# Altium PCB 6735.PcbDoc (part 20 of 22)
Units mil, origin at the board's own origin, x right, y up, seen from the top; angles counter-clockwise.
Board outline 2641.73 x 5165.35 mil, 6 copper layers (Top, Inner Layer 2, Inner Layer 3, Inner Layer 4, Inner Layer 5, Bottom), stack 35.7 mil thick; 1011 components, 790 nets, 4118 pads, 9325 vias.
Unrouted connection lines stored in the file: 4610.
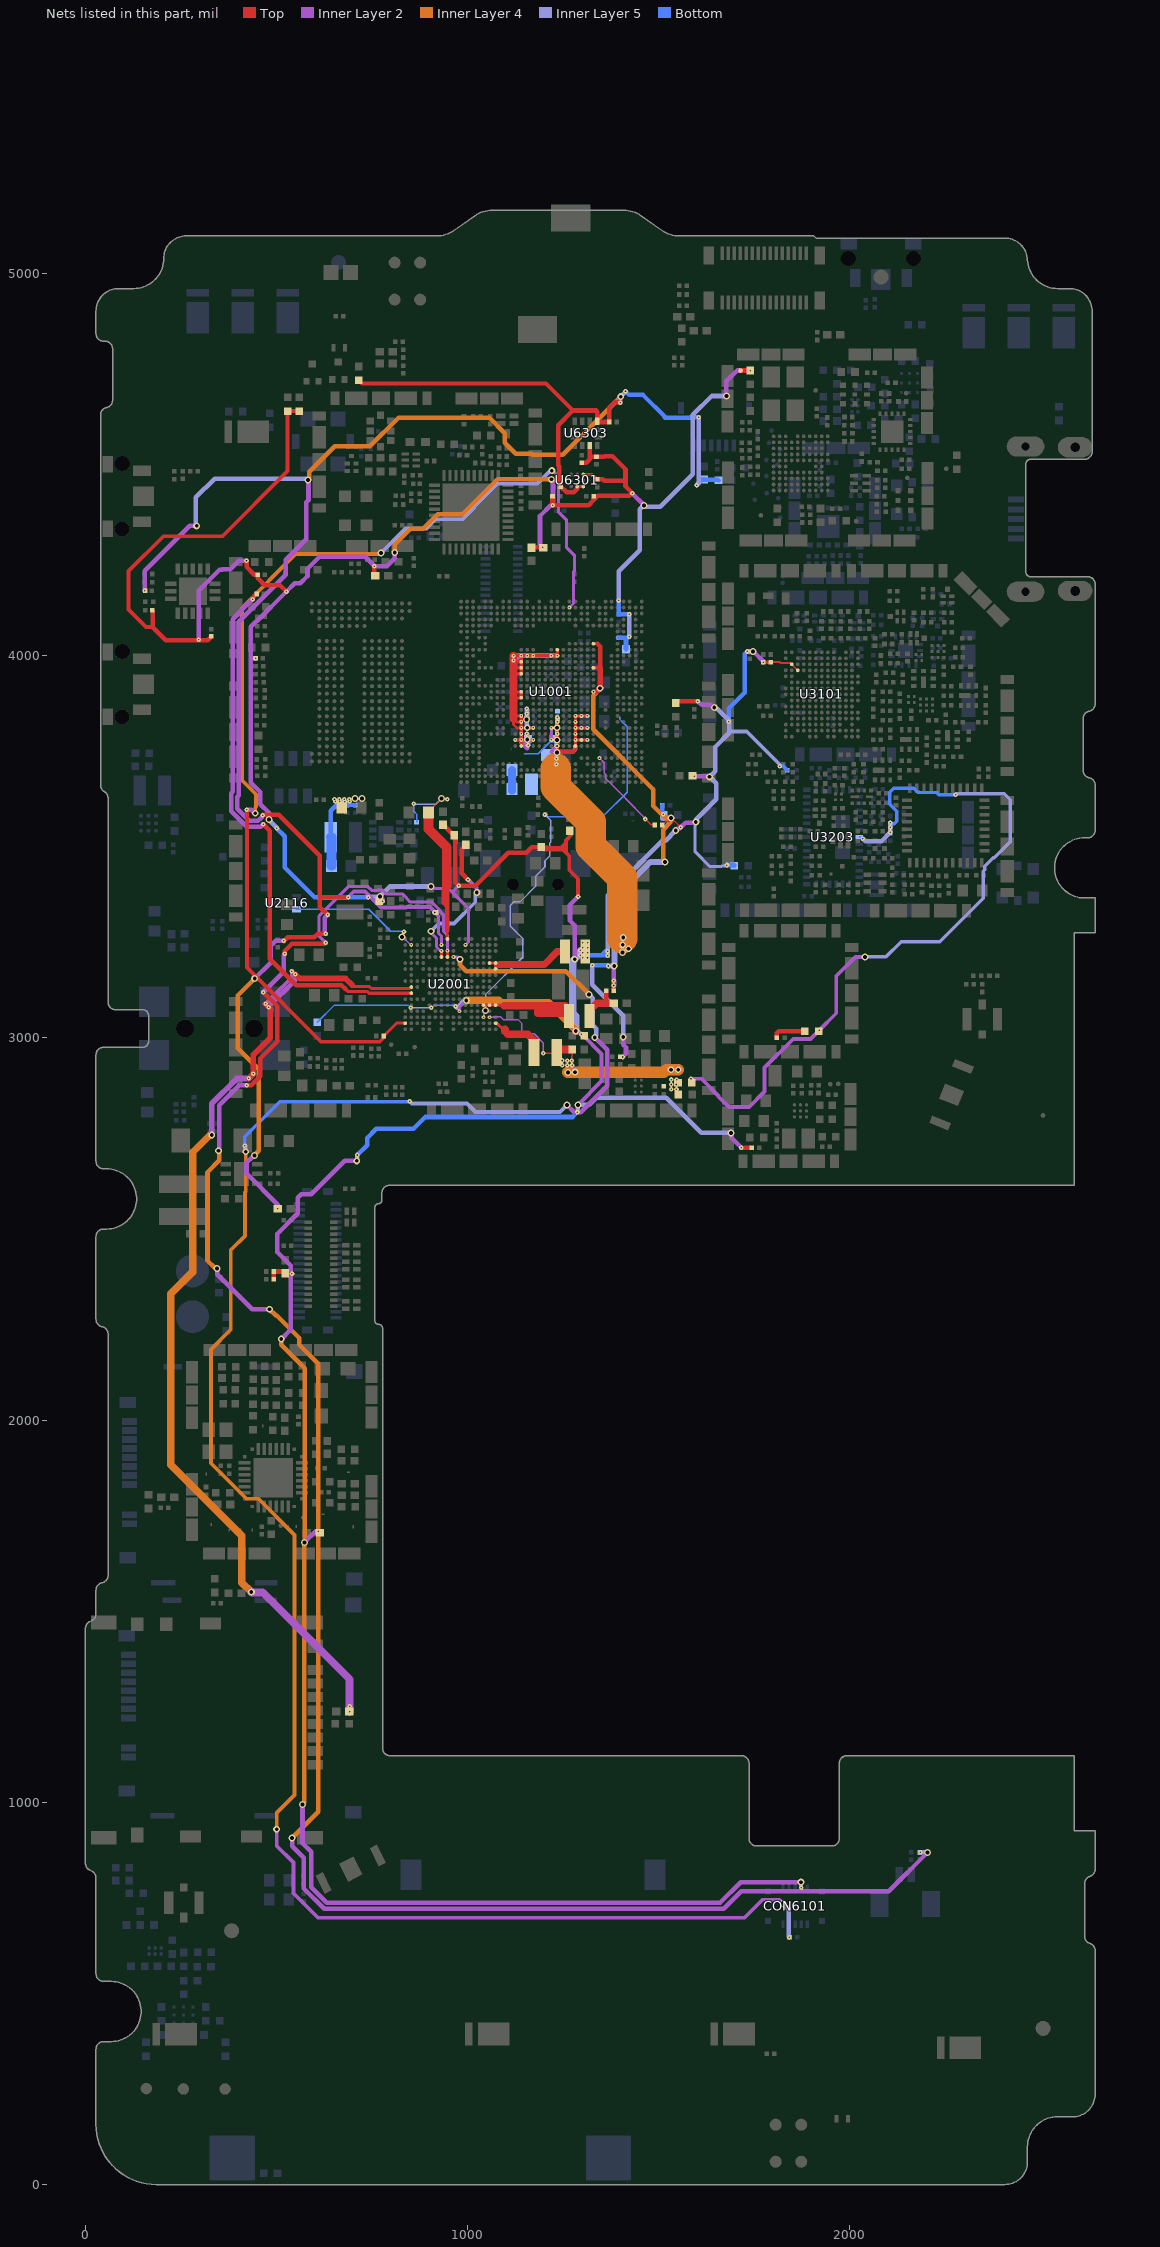
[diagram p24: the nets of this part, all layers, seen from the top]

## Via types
v1: diameter 12, hole 4, Top to Inner Layer 2, 3329 vias
v2: diameter 12, hole 4, Inner Layer 5 to Bottom, 3071 vias
v3: diameter 18, hole 10, Inner Layer 2 to Inner Layer 5, 1928 vias
v4: diameter 10, hole 4, Top to Inner Layer 2, 525 vias
v5: diameter 20, hole 12, Top to Bottom, 472 vias

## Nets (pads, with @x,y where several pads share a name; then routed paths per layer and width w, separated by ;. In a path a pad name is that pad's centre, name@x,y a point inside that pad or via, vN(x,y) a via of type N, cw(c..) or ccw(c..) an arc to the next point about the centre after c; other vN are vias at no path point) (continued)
VCORE_PMU: C10006.1 C10008.1 C10009.1 C10012.1 C10016.1 C10017.1 C10018.1 C10025.1 C10027.1 C10035.1 C10037.1 C10039.1 L2006.2 SH1006.2 U1001.AA8 U1001.AA10 U1001.AA12 U1001.AB8 U1001.AB10 U1001.AB12 U1001.K8 U1001.L7 U1001.L8 U1001.L9 U1001.L10 U1001.L11 U1001.L12 U1001.L15 U1001.L16 U1001.L19 U1001.L20 U1001.L21 U1001.L22 U1001.M8 U1001.M10 U1001.M22 U1001.N8 U1001.N10 U1001.N22 U1001.T8 U1001.T10 U1001.T22 U1001.U7 U1001.U8 U1001.U9 U1001.U10 U1001.U11 U1001.U22 U1001.U23 U1001.Y7 U1001.Y8 U1001.Y9 U1001.Y10 U1001.Y11 U1001.Y12 | length 3265.3
  Top w4: v4(1119.95,3999.49) v4(1119.95,3987.49) 1120.08,3987.36 v4@1120.08,3984.23 ; v4(1140.21,3999.98) v4(1155.96,3999.98) ; U1001.M8@1155.96,3779.51 1165.65,3779.51 ; U1001.M10@1155.96,3811 1163.15,3811 ; U1001.AA8@1297.69,3779.51 1303.15,3779.51 ; v1(1300.76,3209.4) 1302.95,3210.49 L2006.2@1302.95,3220.4 ; v1(1300.85,3235.36) 1301.15,3235.36 1301.15,3248.39 v1(1301.45,3248.39) ; L2006.2@1302.39,3221.26 L2006.2@1301.23,3222.13 ; v1(1313.52,3209.2) 1314.95,3211.49 1314.95,3218.4 L2006.2@1312.07,3221.28 ; v1(1313.98,3248.59) L2006.2@1313.98,3236.06 ; v1(1314.28,3222.22) 1312.97,3222.18 L2006.2@1312.07,3221.28 ; v1(1314.28,3235.96) L2006.2@1313.98,3236.06 ; v1(1300.75,3222.49) L2006.2@1301.02,3222.34 ; v1(1300.75,3222.49) L2006.2@1302.52,3220.83 ; v1(1300.75,3222.49) L2006.2@1301.23,3222.13 ; v1(1300.75,3222.49) L2006.2@1301.24,3222.12 ; v1(1300.75,3222.49) L2006.2@1301.25,3222.12 ; v1(1300.75,3222.49) L2006.2@1300.87,3222.49 ; v1(1300.75,3222.49) L2006.2@1301.03,3222.34 ; v1(1300.75,3222.49) L2006.2@1301.24,3222.12 ; v1(1300.75,3222.49) 1302.65,3220.69 L2006.2@1302.95,3220.4 ; v1(1300.75,3222.49) L2006.2@1301.02,3222.34 ; v1(1300.75,3222.49) L2006.2@1301.09,3222.27 ; v1(1300.75,3222.49) 1302.5,3223.31 1302.18,3223.15 L2006.2@1302.52,3223.32 ; v1(1300.75,3222.49) L2006.2@1301.22,3222.66 ; L2006.2@1300.87,3222.49 L2006.2@1301.02,3222.34 ; L2006.2@1300.87,3222.49 L2006.2@1301.3,3222.49 ; L2006.2@1300.87,3222.49 L2006.2@1301.22,3222.66 ; L2006.2@1300.87,3222.49 L2006.2@1301.22,3222.66 ; L2006.2@1301.02,3222.34 L2006.2@1301.3,3222.49 ; L2006.2@1301.03,3222.34 L2006.2@1301.09,3222.27 ; L2006.2@1301.02,3222.34 L2006.2@1301.15,3222.27 ; L2006.2@1301.03,3222.34 L2006.2@1301.31,3222.18 ; L2006.2@1301.02,3222.34 L2006.2@1301.15,3222.27 ; L2006.2@1301.02,3222.34 L2006.2@1301.3,3222.49 ; L2006.2@1301.09,3222.27 L2006.2@1301.23,3222.13 ; L2006.2@1301.09,3222.27 L2006.2@1301.27,3222.15 ; L2006.2@1301.15,3222.27 L2006.2@1301.31,3222.18 ; L2006.2@1301.15,3222.27 L2006.2@1301.31,3222.18 ; L2006.2@1301.22,3222.66 L2006.2@1302.52,3223.15 ; L2006.2@1301.22,3222.66 L2006.2@1302.52,3223.32 ; L2006.2@1301.22,3222.66 L2006.2@1302.52,3223.32 ; L2006.2@1301.25,3222.12 L2006.2@1302.51,3220.85 ; L2006.2@1301.24,3222.12 L2006.2@1302.52,3221.15 ; L2006.2@1301.25,3222.12 L2006.2@1302.52,3221.15 ; L2006.2@1301.24,3222.12 L2006.2@1302.52,3221.15 ; L2006.2@1301.27,3222.15 L2006.2@1302.52,3221.34 ; L2006.2@1301.31,3222.18 L2006.2@1301.53,3222.05 ; L2006.2@1301.31,3222.18 L2006.2@1301.53,3222.05 ; L2006.2@1301.31,3222.18 L2006.2@1302.52,3221.5 ; L2006.2@1301.31,3222.18 L2006.2@1301.84,3222.49 ; L2006.2@1301.31,3222.18 L2006.2@1301.85,3222.49 ; L2006.2@1301.3,3222.49 L2006.2@1301.84,3222.49 ; L2006.2@1301.3,3222.49 L2006.2@1301.35,3222.52 ; L2006.2@1301.3,3222.49 L2006.2@1302.52,3223.14 ; L2006.2@1301.3,3222.49 L2006.2@1301.35,3222.52 ; L2006.2@1301.35,3222.52 L2006.2@1302.52,3223.15 ; L2006.2@1301.35,3222.52 L2006.2@1302.52,3223.14 ; L2006.2@1301.53,3222.05 L2006.2@1302.52,3221.49 ; L2006.2@1301.53,3222.05 L2006.2@1302.52,3221.49 ; L2006.2@1301.85,3222.49 L2006.2@1302.52,3222.49 ; L2006.2@1301.84,3222.49 L2006.2@1302.52,3222.89 ; L2006.2@1301.85,3222.49 L2006.2@1302.52,3222.89 ; L2006.2@1302.52,3220.83 L2006.2@1302.95,3220.83 ; L2006.2@1302.52,3220.83 L2006.2@1302.52,3221.15 ; L2006.2@1302.52,3220.83 L2006.2@1302.95,3220.4 ; L2006.2@1302.52,3220.83 L2006.2@1302.71,3221.01 ; L2006.2@1302.52,3220.83 L2006.2@1302.71,3221.01 ; L2006.2@1302.52,3221.15 L2006.2@1302.71,3221.01 ; L2006.2@1302.52,3221.15 L2006.2@1302.52,3221.34 ; L2006.2@1302.53,3221.15 L2006.2@1302.71,3221.01 ; L2006.2@1302.53,3221.15 L2006.2@1302.64,3221.26 ; L2006.2@1302.52,3221.34 L2006.2@1302.52,3221.49 ; L2006.2@1302.52,3221.34 L2006.2@1302.64,3221.26 ; L2006.2@1302.53,3221.49 L2006.2@1302.75,3221.36 ; L2006.2@1302.52,3221.49 L2006.2@1302.75,3221.36 ; L2006.2@1302.52,3221.5 L2006.2@1302.52,3222.49 ; L2006.2@1302.52,3222.49 L2006.2@1303.67,3222.49 ; L2006.2@1302.52,3222.49 L2006.2@1302.52,3222.89 ; L2006.2@1302.52,3222.49 L2006.2@1307.53,3225.83 ; L2006.2@1302.52,3222.49 L2006.2@1307.53,3225.83 ; L2006.2@1302.52,3222.89 L2006.2@1302.52,3223.14 ; L2006.2@1302.52,3222.89 L2006.2@1307.53,3225.83 ; L2006.2@1302.52,3222.89 L2006.2@1307.53,3225.83 ; L2006.2@1302.52,3223.15 L2006.2@1302.52,3223.32 ; L2006.2@1302.52,3223.14 L2006.2@1307.53,3225.83 ; L2006.2@1302.52,3223.15 L2006.2@1307.53,3225.83 ; L2006.2@1302.52,3223.15 L2006.2@1307.45,3225.79 ; L2006.2@1302.52,3223.14 L2006.2@1307.53,3225.83 ; L2006.2@1302.52,3223.32 L2006.2@1307.53,3225.83 ; L2006.2@1302.52,3223.32 1302.52,3225.91 1304.99,3228.37 1306.41,3229.8 1312.98,3236.36 L2006.2@1313.98,3236.06 ; L2006.2@1302.52,3223.32 L2006.2@1307.53,3225.83 ; L2006.2@1302.52,3223.32 L2006.2@1304.26,3224.19 ; L2006.2@1302.52,3223.32 L2006.2@1304.26,3224.19 ; L2006.2@1302.52,3223.32 L2006.2@1307.45,3225.79 ; L2006.2@1302.53,3221.5 L2006.2@1302.76,3221.37 ; L2006.2@1302.53,3221.5 L2006.2@1303.67,3222.49 ; L2006.2@1302.53,3221.5 L2006.2@1303.68,3222.49 ; L2006.2@1302.64,3221.26 L2006.2@1302.83,3221.14 ; L2006.2@1302.64,3221.26 L2006.2@1302.75,3221.36 ; L2006.2@1302.71,3221.01 L2006.2@1302.95,3220.83 ; L2006.2@1302.71,3221.01 L2006.2@1302.95,3220.83 ; L2006.2@1302.71,3221.01 L2006.2@1302.83,3221.14 ; L2006.2@1302.71,3221.01 L2006.2@1302.83,3221.14 ; L2006.2@1302.71,3221.01 L2006.2@1302.84,3221.14 ; L2006.2@1302.75,3221.36 1302.9,3221.28 L2006.2@1302.75,3221.36 ; L2006.2@1302.76,3221.37 L2006.2@1302.95,3221.26 ; L2006.2@1302.76,3221.37 L2006.2@1303.96,3222.49 ; L2006.2@1302.84,3221.14 L2006.2@1302.95,3221.06 ; L2006.2@1302.84,3221.14 L2006.2@1302.95,3221.25 ; L2006.2@1302.83,3221.14 L2006.2@1302.95,3221.26 ; L2006.2@1302.84,3221.15 L2006.2@1302.95,3221.26 ; L2006.2@1302.84,3221.15 L2006.2@1302.95,3221.26 ; L2006.2@1302.84,3221.14 L2006.2@1302.95,3221.25 ; L2006.2@1302.95,3220.4 L2006.2@1302.95,3220.83 ; L2006.2@1302.95,3220.4 1304.87,3218.49 1309.27,3218.49 L2006.2@1312.07,3221.27 ; L2006.2@1302.95,3220.4 L2006.2@1303.07,3220.54 ; L2006.2@1302.95,3220.4 L2006.2@1303.07,3220.54 ; L2006.2@1302.95,3220.83 L2006.2@1303.31,3220.83 ; L2006.2@1302.95,3220.83 L2006.2@1302.95,3221.06 ; L2006.2@1302.95,3220.83 L2006.2@1303.09,3220.98 ; L2006.2@1302.95,3221.06 L2006.2@1302.95,3221.25 ; L2006.2@1302.95,3221.06 L2006.2@1303.09,3220.98 ; L2006.2@1302.95,3221.25 L2006.2@1303.32,3221.62 ; L2006.2@1302.95,3221.26 L2006.2@1304.04,3222.34 ; L2006.2@1302.95,3221.26 L2006.2@1304.18,3222.49 ; L2006.2@1302.95,3221.26 L2006.2@1304.06,3222.37 ; L2006.2@1302.95,3221.25 L2006.2@1303.25,3221.55 ; L2006.2@1302.95,3221.26 L2006.2@1304.07,3222.37 ; L2006.2@1303.07,3220.54 L2006.2@1303.31,3220.83 ; L2006.2@1303.07,3220.54 L2006.2@1303.32,3220.83 ; L2006.2@1303.09,3220.98 L2006.2@1303.31,3220.83 ; L2006.2@1303.09,3220.98 L2006.2@1304.47,3222.49 ; L2006.2@1303.09,3220.98 L2006.2@1304.47,3222.49 ; L2006.2@1303.25,3221.55 1303.19,3221.49 L2006.2@1303.61,3221.91 ; L2006.2@1303.25,3221.55 L2006.2@1303.32,3221.62 ; L2006.2@1303.25,3221.55 L2006.2@1303.61,3221.91 ; L2006.2@1303.32,3220.83 1304.18,3220.83 L2006.2@1305.84,3222.49 ; L2006.2@1303.31,3220.83 L2006.2@1304.23,3221.91 ; L2006.2@1303.31,3220.83 L2006.2@1304.23,3221.91 ; L2006.2@1303.32,3220.83 L2006.2@1304.71,3222.49 ; L2006.2@1303.31,3220.83 L2006.2@1304.51,3222.25 ; L2006.2@1303.31,3220.83 L2006.2@1304.71,3222.49 ; L2006.2@1303.32,3221.62 L2006.2@1304.04,3222.34 ; L2006.2@1303.32,3221.62 L2006.2@1304.19,3222.49 ; L2006.2@1303.61,3221.91 L2006.2@1304.19,3222.49 ; L2006.2@1303.61,3221.91 L2006.2@1304.19,3222.49 ; L2006.2@1303.68,3222.49 L2006.2@1303.96,3222.49 ; L2006.2@1303.67,3222.49 L2006.2@1307.53,3225.83 ; L2006.2@1303.68,3222.49 L2006.2@1307.53,3225.83 ; L2006.2@1303.96,3222.49 L2006.2@1304.18,3222.49 ; L2006.2@1303.96,3222.49 L2006.2@1307.53,3225.83 ; L2006.2@1304.04,3222.34 L2006.2@1304.18,3222.49 ; L2006.2@1304.07,3222.37 L2006.2@1304.18,3222.49 ; L2006.2@1304.06,3222.37 L2006.2@1304.18,3222.49 ; L2006.2@1304.07,3222.37 L2006.2@1304.18,3222.49 ; L2006.2@1304.23,3221.91 L2006.2@1304.71,3222.49 ; L2006.2@1304.23,3221.91 L2006.2@1304.51,3222.25 ; L2006.2@1304.19,3222.49 L2006.2@1304.47,3222.49 ; L2006.2@1304.18,3222.49 L2006.2@1307.53,3225.83 ; L2006.2@1304.19,3222.49 L2006.2@1305.94,3224.25 ; L2006.2@1304.18,3222.49 L2006.2@1305.94,3224.25 ; L2006.2@1304.19,3222.49 L2006.2@1306.06,3224.36 ; L2006.2@1304.18,3222.49 L2006.2@1305.98,3224.28 ; L2006.2@1304.19,3222.49 L2006.2@1307.53,3225.83 ; L2006.2@1304.18,3222.49 L2006.2@1305.99,3224.29 ; L2006.2@1304.18,3222.49 L2006.2@1306.16,3224.46 ; L2006.2@1304.26,3224.19 L2006.2@1307.53,3225.83 ; L2006.2@1304.26,3224.19 L2006.2@1307.53,3225.83 ; L2006.2@1304.47,3222.49 L2006.2@1304.71,3222.49 ; L2006.2@1304.47,3222.49 L2006.2@1305.07,3223.14 ; L2006.2@1304.47,3222.49 L2006.2@1305.07,3223.14 ; L2006.2@1304.47,3222.49 L2006.2@1307.53,3225.83 ; L2006.2@1304.51,3222.25 L2006.2@1304.71,3222.49 ; L2006.2@1304.51,3222.25 L2006.2@1304.71,3222.49 ; L2006.2@1304.71,3222.49 L2006.2@1305.84,3222.49 ; L2006.2@1304.71,3222.49 L2006.2@1305.06,3222.91 ; L2006.2@1304.71,3222.49 L2006.2@1307.53,3225.83 ; L2006.2@1304.71,3222.49 L2006.2@1307.53,3225.83 ; L2006.2@1304.71,3222.49 L2006.2@1305.06,3222.91 ; L2006.2@1304.71,3222.49 L2006.2@1307.53,3225.83 ; L2006.2@1304.71,3222.49 L2006.2@1307.53,3225.83 ; L2006.2@1305.06,3222.91 L2006.2@1307.53,3225.83 ; L2006.2@1305.06,3222.91 L2006.2@1307.53,3225.83 ; L2006.2@1305.07,3223.14 L2006.2@1307.53,3225.83 ; L2006.2@1305.07,3223.14 L2006.2@1307.53,3225.83 ; L2006.2@1305.84,3222.49 1307.52,3222.49 L2006.2@1307.52,3224.17 ; L2006.2@1305.84,3222.49 L2006.2@1307.52,3224.17 ; L2006.2@1305.84,3222.49 1307.44,3225.66 L2006.2@1307.53,3225.83 ; L2006.2@1305.84,3222.49 1307.45,3225.67 L2006.2@1307.53,3225.83 ; L2006.2@1305.94,3224.25 L2006.2@1306.06,3224.36 ; L2006.2@1305.99,3224.29 L2006.2@1306.16,3224.46 ; L2006.2@1305.98,3224.28 L2006.2@1306.08,3224.39 ; L2006.2@1305.99,3224.29 L2006.2@1306.1,3224.4 ; L2006.2@1306.06,3224.36 L2006.2@1307.53,3225.83 ; L2006.2@1306.1,3224.4 L2006.2@1306.24,3224.55 ; L2006.2@1306.08,3224.39 L2006.2@1307.53,3225.83 ; L2006.2@1306.1,3224.4 L2006.2@1307.53,3225.83 ; L2006.2@1306.16,3224.46 L2006.2@1307.53,3225.83 ; L2006.2@1306.16,3224.46 L2006.2@1306.24,3224.55 ; L2006.2@1306.24,3224.55 L2006.2@1307.53,3225.83 ; L2006.2@1306.24,3224.55 L2006.2@1307.53,3225.83 ; L2006.2@1307.53,3225.83 L2006.2@1307.53,3225.83 ; L2006.2@1307.53,3225.83 L2006.2@1307.53,3225.83 ; L2006.2@1307.53,3225.83 L2006.2@1307.53,3225.83 ; L2006.2@1307.53,3225.83 L2006.2@1307.53,3225.83 ; L2006.2@1307.53,3225.83 L2006.2@1307.53,3225.83 ; L2006.2@1307.53,3225.83 L2006.2@1307.53,3225.83 ; L2006.2@1307.53,3225.83 L2006.2@1307.53,3225.83 ; L2006.2@1307.52,3224.17 L2006.2@1308.35,3225 ; L2006.2@1307.52,3224.17 L2006.2@1307.53,3225.83 ; L2006.2@1307.52,3224.17 L2006.2@1307.53,3225.83 ; L2006.2@1307.53,3225.83 L2006.2@1308.35,3225 ; L2006.2@1307.53,3225.83 L2006.2@1308.35,3225 ; L2006.2@1307.53,3225.83 L2006.2@1308.07,3225.28 ; L2006.2@1307.53,3225.83 L2006.2@1308.07,3225.28 ; L2006.2@1307.53,3225.83 L2006.2@1307.82,3226.3 ; L2006.2@1307.53,3225.83 L2006.2@1307.82,3226.3 ; L2006.2@1307.82,3226.3 L2006.2@1313.98,3236.06 ; L2006.2@1307.82,3226.3 L2006.2@1313.98,3236.06 ; L2006.2@1308.07,3225.28 L2006.2@1308.35,3225 ; L2006.2@1308.07,3225.28 L2006.2@1308.35,3225 ; L2006.2@1308.35,3225 L2006.2@1309.13,3224.22 ; L2006.2@1308.35,3225 L2006.2@1308.71,3224.64 ; L2006.2@1308.35,3225 L2006.2@1312.07,3221.28 ; L2006.2@1308.35,3225 L2006.2@1308.71,3224.64 ; L2006.2@1308.35,3225 1313.98,3230.63 L2006.2@1313.98,3236.06 ; L2006.2@1308.71,3224.64 L2006.2@1309.13,3224.22 ; L2006.2@1308.71,3224.64 1310.87,3222.49 L2006.2@1309.13,3224.22 ; L2006.2@1309.13,3224.22 L2006.2@1312.07,3221.28
  Top w8: v4(1119.95,3999.49) 1120.08,3999.97 v4(1140.21,3999.98) ; 1120.08,3842.49 v4(1140.21,3842.5) v4(1140.21,3826.75) ; 1120.08,3889.74 U1001.L15@1140.21,3889.74 U1001.L16@1140.21,3905.49 1124.95,3905.49 ; 1120.08,3952.73 U1001.L19@1140.21,3952.73 U1001.L20@1140.21,3968.48 ; 1120.08,3968.48 U1001.L20@1140.21,3968.48 ; v4@1120.08,3984.23 U1001.L21@1140.21,3984.23 ; v4(1124.46,3779.51) v4(1140.21,3779.51) ; U1001.M8@1155.96,3779.51 v4(1140.21,3779.51) ; 1165.65,3779.51 v4(1171.71,3779.51) ; v4(1171.71,3811) 1163.15,3811 U1001.M10@1155.96,3811 v4(1140.21,3811) ; v4(1218.95,3811) U1001.U10@1234.7,3811 ; 1234.7,3748.23 v4(1234.7,3763.76) U1001.U8@1234.7,3779.51 ; v4(1234.7,3826.75) U1001.U10@1234.7,3811 ; U1001.U23@1234.7,4015.73 v4(1234.7,3999.98) v4(1218.95,3999.98) v4(1171.71,3999.98) v4(1155.96,3999.98) v4(1140.21,3999.98) ; 1275.08,3748.23 1281.94,3755.1 ; U1001.Y7@1281.94,3763.76 1281.94,3755.1 ; v4(1313.44,3779.51) 1303.15,3779.5 U1001.AA8@1297.69,3779.51 v4(1281.94,3779.51) ; v4(1313.44,3811) v4(1297.69,3811) v4(1281.94,3811) ; v4(1313.44,3842.5) v4(1297.69,3842.5) v4(1281.94,3842.5) v4(1281.94,3811) ; 1128.44,3826.75 v4(1140.21,3826.75) ; 1128.44,3826.75 1120.08,3835.1 1120.08,3820.1 1129.19,3811 v4(1140.21,3811) ; 1128.44,3826.75 v4(1140.21,3826.75) ; U1001.L7@1140.21,3763.76 1139.65,3763.2 U1001.L7@1140.21,3763.76 ; U1001.L7@1140.21,3763.76 v4(1140.21,3779.51) ; v4(1140.21,3779.51) v4(1140.21,3795.25) v4(1140.21,3811) ; v4(1140.21,3811) v4(1140.21,3826.75) ; U1001.L20@1140.21,3968.48 U1001.L21@1140.21,3984.23 ; U1001.L21@1140.21,3984.23 v4(1140.21,3999.98) ; U1001.U8@1234.7,3779.51 v4(1218.95,3779.51) U1001.U8@1234.7,3779.51 ; U1001.U8@1234.7,3779.51 v4(1234.7,3795.25) ; U1001.U8@1234.7,3779.51 v4(1234.7,3795.25) ; U1001.U8@1234.7,3779.51 v4(1234.7,3795.25) ; v4(1234.7,3795.25) U1001.U10@1234.7,3811 ; v4(1234.7,3795.25) U1001.U10@1234.7,3811 ; v4(1234.7,3795.25) U1001.U10@1234.7,3811 ; 1281.94,3755.1 v4(1281.94,3779.51) ; v4(1281.94,3779.51) v4(1281.94,3795.25) v4(1281.94,3811)
  Top w12: 1234.7,3748.23 1275.08,3748.23
  Top w20: v4(1119.95,3999.49) 1119.95,3999.84 1120.08,3999.97 v4@1120.08,3987.36 ; 1120.08,3835.1 1120.08,3842.49 1120.08,3889.74 1120.08,3952.73 1120.08,3968.48 v4@1120.08,3984.23
  Inner Layer 2 w4: v4(1119.95,3987.49) 1121.61,3989.15 1125.61,3993.15 1125.61,3994.63 1130.96,3999.98 1139.44,3999.98 v4(1140.21,3999.98)
  Inner Layer 2 w8: v4@1118.95,3989.15 1119.95,3989.15 1121.61,3989.15 1128.62,3989.15 1139.44,3999.98 1139.83,4000.36 v4@1139.95,4000.49 ; v4(1124.46,3779.51) v4(1140.21,3779.51) 1155.95,3779.5 1156.29,3779.5 1157.9,3779.5 v4(1171.71,3779.51) ; v3(1155.95,3811.49) 1155.95,3811.24 1171.71,3811.24 v4(1171.71,3811) ; v4(1218.95,3811) v4(1218.95,3779.51) 1233.68,3779.5 v3@1234.08,3779.1 ; 1281.94,3763.75 v4(1281.94,3779.51) ; v4(1281.94,3811) v4(1313.44,3811) ; v4(1313.44,3779.51) v4(1281.94,3779.51) ; v4(1313.44,3842.5) v4(1281.94,3842.5) v4(1281.94,3826.75) v4(1281.94,3779.51)
  Inner Layer 2 w10: v4(1119.95,3987.49) 1119.95,3989.15 1119.95,3990.15 v4@1119.95,3991.49 ; v4@1119.95,3991.49 v4(1119.95,3999.49) 1127.95,3999.49 v4@1119.95,3991.49
  Inner Layer 2 w12: v4(1140.21,3779.51) 1140.21,3774.04 1155.95,3758.3 1155.95,3779.5 v3(1155.95,3780.49) ; v4(1140.21,3999.98) v4@1139.95,4000.49 ; v3(1233.95,3779.49) v3@1234.08,3779.1 ; v4(1234.7,3763.76) 1225.7,3754.75 1219.56,3748.62 1275.46,3748.62 1281.94,3755.1 1281.94,3763.75 ; v4(1234.7,3999.98) 1234.19,4000.49 v4@1139.95,4000.49 ; 1130.28,4000.49 v4@1139.95,4000.49 ; 1130.28,4000.49 1120.95,4000.49 v4(1119.95,3999.49) 1118.95,3998.49 1118.95,3989.15 1119.95,3990.15 1124.62,3994.82 1130.28,4000.49 ; v3(1155.95,3780.49) 1157.9,3779.5 1156.7,3778.3 1156.29,3779.5 v3(1155.95,3780.49)
  Inner Layer 4 w4: 1230.06,3705.5 1230.06,3718.55 1233.95,3722.44 v3(1233.95,3746.49) ; 1404.95,3253.31 1404.95,3260.49 v3(1406.95,3262.49)
  Inner Layer 4 w80: 1230.06,3705.5 1230.06,3657.29 1322.06,3565.29 1322.06,3501.76 1404.95,3418.87 v3@1404.95,3260.49
  Inner Layer 5 w10: v3(1233.95,3746.49) 1233.95,3761.49 v2(1232.31,3763.09) 1233.95,3763.09 1233.95,3769.49 ; v3(1233.95,3779.49) v2(1233.95,3795.49) v3(1233.95,3811.49) v2(1233.95,3827.49) v2(1233.95,3839.49)
  Inner Layer 5 w12: v2(1154.95,3795.49) 1155.45,3795.49 1155.45,3780.49 v3(1155.95,3780.49) 1157.95,3780.49 v2(1157.95,3765.49) ; v2(1154.95,3848.49) v3@1154.95,3833.49 ; v2(1154.95,3861.49) v2@1154.95,3860.49 ; v3@1155.34,3833.23 1155.12,3848.49 v2@1154.95,3860.49 ; v3(1155.95,3811.49) 1154.95,3811.49 v3@1154.95,3832.73 ; v2(1232.16,3716.46) 1232.16,3767.69 1233.95,3769.49 v3(1233.95,3779.49) ; v3@1153.95,3831.49 v3(1154.01,3833.21) ; v3@1153.95,3831.49 1153.95,3833.21 v3(1154.01,3833.21) ; v3@1153.95,3831.49 1154.82,3832.56 v3@1154.95,3832.73 ; v3(1154.01,3833.21) v3@1154.95,3832.73 ; v3(1154.01,3833.21) v3@1154.95,3833.49 ; v3(1154.01,3833.21) v3@1154.95,3833.21 ; v3(1154.01,3833.21) 1154.54,3848.5 v2@1154.95,3860.49 ; v3@1154.95,3832.73 v3@1155.34,3833.21 ; v3@1154.95,3832.73 v3@1155.34,3833.21 ; v3@1154.95,3832.73 v3@1154.95,3833.21 ; v3@1154.95,3833.21 v3@1155.34,3833.21 ; v3@1154.95,3833.21 v3@1154.95,3833.49 ; v3@1154.95,3833.49 v3@1155.34,3833.21
  Bottom w4: SH1006.2@1150.95,3743.49 1184.95,3743.49 C10016.1@1223.95,3782.49
  Bottom w20: C10008.1@1115.9,3701.09 C10009.1@1115.9,3651.09 ; C10009.1@1115.9,3651.09 1115.9,3647.09 C10009.1@1115.9,3651.09
  other v2: 1232.28,3730.99
  other v3: 1405.38,3223.19 1421.12,3233.31 1405.87,3243.53
VCORE_SW: L2006.1 U2001.A5 U2001.A6 U2001.B5 | length 283.3
  Top w4: 1079.37,3188.31 1083.06,3192
  Top w8: U2001.B5@1057.32,3195.95 U2001.A5@1073.06,3195.95 ; U2001.A5@1073.06,3195.95 1079.37,3189.64 ; U2001.A5@1073.06,3195.95 1079.37,3189.64 ; U2001.A5@1073.06,3195.95 1085.83,3195.95 1089.78,3192 1089.95,3191.83 1084.69,3191.83 1079.37,3186.51 ; U2001.A5@1073.06,3195.95 U2001.A6@1073.06,3180.2 1079.37,3186.51 ; 1079.37,3186.51 1079.37,3188.31 1079.37,3189.64
  Top w19: 1083.06,3192 1089.78,3192 1200.73,3192 1234.56,3225.83 L2006.1@1254.38,3225.83
VDC_ET: C3291.1 R3220.2 | length 122.5
  Top w4: R3220.2@1881.26,3018.61 1880.21,3017.56 1876.95,3014.3 1876.95,3017.56 1876.95,3022.82 1877.05,3022.82 R3220.2@1881.26,3018.61 ; R3220.2@1881.26,3018.61 1884.81,3022.16 1886.35,3022.16 1882.31,3018.12 R3220.2@1882.31,3017.56 R3220.2@1881.26,3018.61
  Top w12: C3291.1@1809.08,3000.58 1809.08,3012.94 1813.7,3017.56 1876.95,3017.56 1880.21,3017.56 R3220.2@1882.31,3017.56
VDRV: U2001.R2 U2116.2 | length 364
  Top w4: U2001.R2@852.41,3243.19 v4(852.59,3243.19) U2001.R2@852.41,3243.19
  Inner Layer 2 w4: v3(827.94,3263.93) 830.7,3261.58 831.63,3262.51 851.77,3242.37 v4(852.59,3243.19)
  Inner Layer 5 w4: v3(827.94,3263.93) 830.33,3261.58 830.33,3278.83 v2(833.3,3277.96)
  Bottom w4: U2116.2@551.93,3336.34 708.31,3336.34 741.06,3336.34 798.57,3278.83 829.95,3278.83 v2(833.3,3277.96)
VEFUSE: C2048.1 U1001.W30 U2001.T15 | length 2864.6
  Top w8: C2048.1@780.31,3005.09 813.7,3038.47 U2001.T15@836.84,3038.47
  Top w10: v1(422.29,3597.17) 422.31,3585.09 422.31,3184.09 616.31,2990.09 770.04,2990.09 780.31,3000.36 C2048.1@780.31,3005.09
  Inner Layer 2 w8: v3(1220.16,4484.09) 1221.12,4485.05 1237.31,4468.86 1237.31,4376.43 1258.95,4354.79 1258.95,4282.75 1279.89,4261.81 1279.89,4222.83 1276.95,4219.89 1276.95,4136.72 v4(1266.2,4125.96)
  Inner Layer 2 w12: v1(422.29,3597.17) 433.48,3597.17 444.27,3586.38 v3(444.27,3587.68)
  Inner Layer 4 w10: v3(444.27,3587.68) 444.27,3603.52 445.95,3605.2 445.95,3637.42 409.31,3674.06 409.31,4125.62 549.53,4265.83 770.06,4265.83 v3(773.31,4269.09)
  Inner Layer 5 w10: v3(773.31,4269.09) 837.31,4333.09 892.53,4333.09 916.53,4357.09 986.53,4357.09 1016.31,4386.88 1016.31,4388.3 1078.1,4450.09 1182.36,4450.09 1218.26,4485.99 v3(1220.16,4484.09)
VEMC_3V3_PMU: R4101.2 U2001.R10 | length 1468.8
  Top w4: R4101.2@446.95,4161.49 446.4,4161.23 446.75,4161.29 R4101.2@447.95,4161.49
  Top w8: 680.95,3126.83 685.95,3121.83 737.06,3121.83 742.06,3116.83 852.59,3116.83 U2001.R10@852.59,3117.21
  Top w12: v1(437.57,4148.09) 437.57,4152.11 446.75,4161.29 R4101.2@446.95,4161.49 ; v1(465.24,3559.16) 482.45,3541.95 482.45,3207.33 551.95,3137.83 669.95,3137.83 680.95,3126.83
  Inner Layer 2 w12: v1(437.57,4148.09) 426.63,4137.14 426.38,4137.14 384.95,4095.71 384.95,3643.87 381.31,3640.23 381.31,3592.89 422.12,3552.09 458.17,3552.09 v1(465.24,3559.16)
VGP1_PMU: C6101.1 CON6101.4 U2001.H4 | length 5335.4
  Top w4: U2001.H4@962.94,3211.81 v4(962.83,3211.7) 962.82,3211.92 U2001.H4@962.94,3211.82
  Inner Layer 2 w8: v4(962.83,3211.7) 974.7,3211.7 980.26,3206.15 v3(979.93,3205.82)
  Inner Layer 2 w10: v3(500.27,929.54) 500.27,886.58 544.31,842.53 544.31,762.09 608.31,698.09 1724.68,698.09 1771.58,744.99 1815.42,744.99 v3(1825.31,735.09)
  Inner Layer 2 w12: v3(1259.8,2824.4) 1278.37,2805.83 1296.18,2805.83 1365.31,2874.96 1365.31,2968.7 1362.31,2971.7 v3(1332.58,3001.44)
  Inner Layer 4 w10: v3(419.31,2702.3) 419.31,2598.32 417.31,2596.32 417.31,2482.18 380.31,2445.18 380.31,2236.94 328.31,2184.94 328.31,1887.01 334.31,1881.01 378.89,1836.43 421.23,1794.09 452.7,1794.09 546.95,1699.84 546.95,1019.09 500.27,972.41 v3(500.27,929.54)
  Inner Layer 4 w12: v3(979.93,3205.82) 979.93,3191.47 996.57,3174.83 1256.72,3174.83 v3(1317.81,3113.75)
  Inner Layer 5 w10: v2(847.95,2833.83) 853.69,2828.09 998.27,2828.09 1020.27,2806.09 1241.49,2806.09 v3(1259.8,2824.4)
  Inner Layer 5 w12: v2(416.69,2718.09) 418,2718.09 418,2702.3 v3(419.31,2702.3) ; v3(1317.81,3113.75) 1327.31,3104.24 1327.31,3033.59 1336.31,3024.59 1336.31,3005.17 v3(1332.58,3001.44) ; v3(1825.31,735.09) 1840.31,720.09 1840.31,648.09 v2(1841.31,647.09)
  Bottom w4: v2(1841.31,647.09) 1841.71,647.49 C6101.1@1841.95,647.49
  Bottom w6: CON6101.4@1840.75,680.7 1840.75,648.68 1841.83,647.61 C6101.1@1841.95,647.49
  Bottom w10: v2(416.69,2718.09) 416.69,2741.34 508.44,2833.09 847.21,2833.09 v2(847.95,2833.83)
VIBR_PMU: R6601.1 U2001.J4 | length 5219.3
  Top w8: v4(946.95,3227.83) 946.95,3211.82 U2001.J4@947.08,3211.7 ; U2001.J4@947.08,3211.7 947.64,3211.13 U2001.J4@947.08,3211.7
  Top w12: v1(421.95,2875.83) 433.95,2875.83 457.31,2899.19 457.31,2946.09 502.31,2991.09 502.31,3082.88 v1(465.35,3119.84) ; v1(521.85,3219.71) 521.85,3227.46 540.22,3245.83 625.96,3245.83 v1(628.78,3248.65)
  Inner Layer 2 w8: v1(628.78,3248.65) 611.31,3266.11 611.31,3319.5 687.65,3395.83 738.97,3395.83 748.71,3386.09 762.62,3386.09 763.62,3387.09 777.53,3387.09 788.53,3376.09 830.11,3376.09 840.31,3365.89 840.31,3364.91 850.13,3355.09 906.91,3355.09 927.18,3334.82 927.18,3331.16 936.31,3322.02 936.31,3279.84 946.95,3269.2 v4(946.95,3227.83)
  Inner Layer 2 w12: v3(344.31,2397.09) 344.31,2382.09 436.31,2290.09 v3(481.31,2290.09) ; v3(348.31,2704.68) 350.31,2704.68 350.31,2823.51 402.63,2875.83 v1(421.95,2875.83) ; v1(465.35,3119.84) 518.35,3172.83 518.35,3216.21 v1(521.85,3219.71) ; v3(540.68,906.91) 540.68,885.3 571.31,854.67 571.31,774.46 624.69,721.09 1670.2,721.09 1716.2,767.09 2101.21,767.09 v3(2202.95,868.83)
  Inner Layer 4 w12: v3(344.31,2397.09) 339.44,2397.09 319.31,2417.22 319.31,2648.68 350.31,2679.68 350.31,2704.68 v3(348.31,2704.68) ; v3(481.31,2290.09) 498.75,2272.65 501.24,2272.65 558.95,2214.95 558.95,2197.47 608.95,2147.47 608.95,975.19 v3(540.68,906.91)
  Inner Layer 5 w12: v2(2183.95,869.83) 2183.95,869.33 2202.95,869.33 v3(2202.95,868.83)
  Bottom w4: R6601.1@2182.95,868.83 2182.95,869.83 v2(2183.95,869.83)
VIO18_PMU: C2058.1 C3105.1 C3106.1 C6303.1 C6314.1 CON6101.7 R1004.2 R1008.2 R1009.2 R1012.2 R1014.2 R1018.2 R1026.2 R1028.2 R1029.2 R1109.2 R1204.1 R1205.1 R1206.1 R1207.1 R1208.1 R1209.1 R2042.1 R3232.1 R3278.1 R3715.1 R3911.1 R4102.2 R6002.1 R6104.2 R6211.1 R6308.2 R6314.1 R6318.1 R6351.1 R6352.1 SH4101.1 SH5109.1 TP3720.1 U2001.F2 U2001.G13 U3101.L4 U3101.M3 U6301.C1 U6303.3 | length 14887.5
  Top w4: v1@294.31,4040.83 294.31,4041.93 v1(296.15,4041.93) ; v1(608.87,1709.02) 608.87,1705.09 SH5109.1@613.31,1705.09 ; R2042.1@768.31,3358.09 768.31,3357.34 v1(778.31,3357.34) ; R1109.2@1509.31,3557.09 1518.64,3566.42 1542.17,3566.42 v1(1557.7,3550.89) ; U3101.M3@1847.91,3977.33 U3101.L4@1863.66,3961.58 ; R1012.2@1196.95,4282.83 1196.95,4283.49 v1(1196.95,4283.83) 1196.95,4285.49 1197.95,4286.49 1197.21,4283.76 1197.13,4283.49 1197.11,4283.39 1197.02,4283.08 R1012.2@1196.95,4282.83 ; U6303.3@1319.8,4549.5 1319.95,4549.34 U6303.3@1319.8,4549.5
  Top w5: C3106.1@1793.15,3983.09 1816.8,3983.09 1818.56,3981.33 1843.91,3981.33 U3101.M3@1847.91,3977.33
  Top w8: U6301.C1@1302.7,4474.24 1326.2,4474.23 C6303.1@1338.95,4461.49
  Top w10: 175.95,4074.82 158.66,4074.82 112.29,4121.19 112.29,4221.23 203.73,4312.66 358.42,4312.66 528.95,4483.2 R6352.1@528.95,4639.99 R6351.1@558.95,4639.99 ; R1028.2@1192.95,3499.49 R1028.2@1192.95,3498.49 ; R1029.2@1267.31,3541.09 1270.49,3541.09 1270.49,3530.37 1256.95,3516.83 1256.95,3510 ; v1(1288.7,3369.3) 1288.7,3416.52 1265.95,3439.27 1265.95,3475.83 1256.95,3484.83 ; v1(1773.25,3982.88) 1793.15,3982.88 C3106.1@1793.15,3983.09 ; R1028.2@1192.95,3498.49 1198.94,3492.5 1239.45,3492.5 ; R1028.2@1192.95,3498.49 1209.29,3498.49 1210.95,3496.83 1243.78,3496.83 ; 1239.45,3492.5 1249.28,3492.5 1256.95,3484.83 ; 1239.45,3492.5 1243.78,3496.83 ; 1243.78,3496.83 1254.95,3496.83 1256.95,3498.83 ; 1243.78,3496.83 1256.95,3510 ; 1256.95,3484.83 1256.95,3498.83 ; 1256.95,3498.83 1256.95,3510
  Top w12: R6308.2@174.95,4118.83 175.95,4117.83 175.95,4074.82 209.94,4040.83 294.31,4040.83 296.15,4040.83 319.95,4040.83 R6318.1@328.95,4049.83 ; v1(421.35,4248.43) 421.95,4232.21 442.06,4212.09 R4102.2@451.31,4212.09 451.31,4203.09 469.57,4184.83 508.95,4184.83 v1(525.95,4167.83) ; R1204.1@492.6,2368.89 R1205.1@492.6,2388.89 516.51,2388.89 R6104.2@522.31,2383.09 ; R6104.2@522.31,2384.09 R6104.2@522.31,2383.09 ; v1(540.31,2383.09) R6104.2@522.31,2383.09 ; v1(755.95,4233.83) 755.95,4209.09 R1008.2@758.31,4209.09 ; R1014.2@935.31,3558.09 935.31,3557.09 935.81,3557.09 935.81,3557.59 964.81,3528.59 964.81,3529.09 R1018.2@965.31,3529.09 ; R1018.2@965.31,3530.09 R1018.2@965.31,3529.09 ; R1026.2@1166.95,4282.49 1166.95,4283.49 R1012.2@1196.95,4283.49 ; R1028.2@1192.95,3498.49 1168.02,3498.49 1153.62,3484.09 1106.48,3484.09 1020.48,3398.09 v1(976.58,3398.09) 967.95,3406.72 967.95,3509.19 968.07,3509.31 968.07,3526.33 R1018.2@965.31,3529.09 ; R1012.2@1197.95,4282.83 1197.11,4283.39 R1012.2@1196.95,4283.49 ; R1012.2@1197.95,4286.49 1197.95,4283.49 1197.13,4283.49 R1012.2@1196.95,4283.49 ; R1207.1@1221.95,4417.49 1221.95,4394.09 v1(1222.31,4394.09) 1247.19,4394.09 1247.45,4393.83 1316.69,4393.83 1330.31,4407.46 ; v1(1296.73,3009.57) 1298.86,3009.57 1303.95,3004.49 1303.95,3005.49 C2058.1@1304.95,3005.49 ; R1206.1@1297.95,4504.49 1309.95,4504.49 1319.79,4514.33 1319.79,4520.49 ; U6303.3@1319.8,4549.5 1319.79,4520.49 ; R6211.1@1330.31,4417.09 1330.31,4407.46 ; C6303.1@1338.95,4461.49 1353.87,4461.49 1357.27,4458.09 1412.96,4458.09 ; R6314.1@1544.31,3876.09 1544.31,3881.09 v1(1602.31,3881.09) ; TP3720.1@1714.31,4746.09 v1(1739.31,4746.09) ; v1(1716.31,2712.56) 1729.29,2712.56 ; 1729.31,2712.58 R3911.1@1743.08,2712.58 ; 1319.79,4520.49 C6314.1@1336.95,4520.49 1357.71,4520.49 1359.31,4522.09 1378.93,4522.09 1412.96,4488.06 1412.96,4458.09 ; 1330.31,4407.46 1340.95,4418.09 1422.97,4418.09 v1(1430.25,4425.38) 1430.25,4425.8 1412.96,4443.09 1412.96,4458.09
  Inner Layer 2 w4: v1@1196.12,4284.66 1197.95,4286.49 v1(1196.95,4283.83)
  Inner Layer 2 w8: v3(903.75,3396.09) 908.75,3391.09 949.65,3391.09 959.29,3381.45 ; v1(976.58,3398.09) 975.93,3398.09 959.29,3381.45 ; v4(978.57,3069.96) 978.95,3069.83 978.95,3081.15 995.89,3098.09 v3(996.49,3097.53) ; v4(994.32,3243.19) 1002.31,3251.19 1002.31,3338.83 983.32,3357.83 982.91,3357.83 961.95,3378.79 ; 959.29,3381.45 961.95,3378.79 ; 959.29,3381.45 961.95,3378.79
  Inner Layer 2 w10: v3(1288.31,2824.83) 1350.31,2886.83 1350.31,2958.09 1298.83,3009.57 v1(1296.73,3009.57)
  Inner Layer 2 w12: v1(296.15,4041.93) 296.15,4170.66 350.58,4225.09 357.57,4225.09 358.31,4225.83 379.03,4225.83 401.63,4248.43 v1(421.35,4248.43) ; v1(444.95,3993.49) 444.95,3993.83 432.95,3993.83 ; v3(480.31,3571.09) 480.31,3588.72 457.31,3611.72 457.31,3643.47 432.95,3667.83 432.95,3993.83 ; v3(512.31,2212.09) 537.31,2237.09 v1@537.31,2380.09 ; v1(540.31,2383.09) v1@537.31,2380.09 ; v3(567.93,994.11) 567.93,893.16 590.31,870.78 590.31,778.09 631.31,737.09 1660.31,737.09 1714.31,791.09 v3(1872.31,791.09) ; v3(573.21,1680.18) 602.05,1709.02 v1(608.87,1709.02) ; v3(709.84,2678.4) 709.84,2678.51 678.54,2678.51 591.12,2591.09 564.69,2591.09 555.31,2581.71 555.31,2540.92 502.31,2487.92 502.31,2439.59 537.31,2404.59 v1@537.31,2380.09 ; v3(770.31,3370.09) 778.31,3362.09 v1(778.31,3357.34) ; v3(809.31,4270.09) 809.31,4254.46 788.94,4234.09 v1@756.21,4234.09 ; v1(1196.95,4283.83) 1196.12,4284.66 1189.31,4291.47 1189.31,4365.57 1217.84,4394.09 v1(1222.31,4394.09) 1223.31,4394.09 1223.31,4457.67 v3(1219.49,4461.49) ; v3(1279.95,3205.83) 1279.95,3294.22 1267.62,3306.56 1267.62,3348.22 v1(1288.7,3369.3) ; v3(1282.95,3018.09) 1288.24,3018.06 v1(1296.73,3009.57) ; v1(1430.25,4425.38) 1430.03,4425.15 1461.96,4393.22 v3(1461.73,4393) ; v3(1544.56,3542.8) 1544.51,3542.85 1548.49,3546.83 1553.64,3546.83 v1(1557.7,3550.89) 1570.04,3563.23 1595.31,3563.23 v3(1596.96,3564.88) ; v1(1592.3,3684.09) 1633.04,3684.09 v3(1633.04,3683.13) ; v1(1602.31,3881.09) 1611.91,3871.49 1633.74,3871.49 1636.75,3868.48 1641.65,3868.48 1647.5,3862.63 1647.45,3862.57 1646.9,3862.57 1645.05,3864.42 v3(1645.34,3864.71) ; v3(1676.9,4679.53) 1676.9,4717.68 1705.3,4746.09 v1(1739.31,4746.09) ; v3(1689.31,2751.56) 1689.31,2739.56 v1(1716.31,2712.56) ; v3(1746.15,4011.09) 1748.15,4011.09 1747.97,4010.9 1774.62,3984.25 v1(1773.25,3982.88) ; 432.95,3993.83 432.95,4075.83 446.95,4089.83 447.95,4089.83 v1(525.95,4167.83) 547.95,4189.83 562.36,4189.83 580.95,4208.42 580.95,4227.34 612.44,4258.83 731.92,4258.83 756.44,4234.32 v1@756.21,4234.09 ; v1@756.21,4234.09 v1(755.95,4233.83) 755.95,4234.09 v1@756.21,4234.09
  Inner Layer 4 w4: v3(573.21,1680.18) 573.21,1691.25 573.71,1691.75
  Inner Layer 4 w12: v3(512.31,2212.09) 512.31,2196.83 573.71,2135.43 573.71,1691.75 573.71,1680.24 572.95,1679.48 572.95,999.13 v3(567.93,994.11) ; v3(809.31,4270.09) 809.31,4291.83 849.55,4332.07 884.12,4332.07 922.14,4370.09 987.31,4370.09 1078.71,4461.49 v3(1219.49,4461.49)
  Inner Layer 4 w20: v3(996.49,3097.53) 996.49,3098.09 1080.78,3098.09 1086.78,3092.09 1165.7,3092.09 1165.96,3091.83 1212.48,3091.83 1282.95,3021.36 v3(1282.95,3018.09)
  Inner Layer 5 w4: v2(851.15,3078.7) 877.88,3078.7 v2(904.64,3078.68)
  Inner Layer 5 w8: v3@1600.17,3568.09 v3(1596.96,3564.88) 1595.15,3563.07 1595.15,3487.07 1634.2,3448.02 1664.05,3448.02 1664.05,3450.16 1678.46,3450.16 v2(1678.46,3452.31)
  Inner Layer 5 w10: 1684.3,3798.09 1688.3,3802.09 1729.99,3802.09 1816.5,3715.58 1816.5,3711.09 v2(1816.65,3711.09) ; v2(1872.31,776.09) v3(1872.31,791.09)
  Inner Layer 5 w12: v3(480.31,3571.09) 479.65,3570.42 501.39,3548.67 v2(500.73,3548.01) ; v3(709.84,2678.4) 711.31,2678.51 711.31,2688.09 v2(711.33,2693.61) ; v2(740.31,3368.09) 740.31,3369.09 770.31,3369.09 v3(770.31,3370.09) 796.31,3396.09 v3(903.75,3396.09) ; v2(969.31,3082.29) 972.01,3079.59 993.2,3100.79 995.89,3098.09 v3(996.49,3097.53) ; v2(1287.31,2806.09) 1287.81,2806.09 1287.81,2824.83 v3(1288.31,2824.83) 1317.94,2824.83 1336.11,2843 1519.56,2843 1611,2751.56 v3(1689.31,2751.56) ; v2(1294.81,3228.88) 1294.73,3228.88 1294.73,3220.61 1294.73,3216.09 v2(1294.31,3216.09) ; v2(1366.04,3214.91) v2(1366.04,3227.15) 1366.04,3372.74 1509.47,3516.17 1517.93,3516.17 v3(1544.56,3542.8) ; v2(1394.95,4144.49) 1394.95,4220.89 1450.31,4276.25 1450.31,4383 v3@1456.72,4389.4 ; v2(1422.54,4108.8) 1422.54,4108.49 1422.86,4108.49 v2(1422.86,4050.06) ; v3(1461.73,4393) 1460.31,4393 v3@1456.72,4389.4 ; v3@1600.17,3568.09 1597,3571.27 1650.12,3624.39 1650.12,3666.04 v3(1633.04,3683.13) 1647.31,3697.4 1647.31,3761.1 1684.3,3798.09 v2@1684.3,3828.1 ; v3(1645.34,3864.71) 1645.05,3864.42 1648.27,3861.2 1652.99,3861.2 1684.3,3829.89 v2@1684.3,3828.1 ; v3(1676.9,4679.53) 1638.37,4679.53 1588.95,4630.12 1588.95,4474.74 1503.61,4389.4 v3@1456.72,4389.4 ; v2(1683.31,3827.09) v2@1684.3,3828.1 ; v2(1731.15,4011.09) v3(1746.15,4011.09) ; v3@1282,3205.83 v3(1279.95,3205.83) 1280.98,3204.81 v3@1282,3205.83 ; v3@1282,3205.83 1284.05,3205.83 v2(1294.31,3216.09) ; v3@1282,3205.83 1293.29,3217.12 v2(1294.31,3216.09)
  Inner Layer 5 w18: v3(1279.95,3205.83) 1294.73,3220.61 1294.81,3220.69 v2(1294.81,3228.88)
  Inner Layer 5 w20: v3(1279.95,3205.83) 1275.07,3200.95 1275.07,3064.63 1282.84,3056.86 1282.84,3023.6 1282.95,3023.49 v3(1282.95,3018.09)
  Bottom w4: R6002.1@606.31,3041.09 651.29,3086.07 843.79,3086.07 v2(851.15,3078.7) ; v2(904.64,3078.68) 911.69,3085.72 965.88,3085.72 v2(969.31,3082.29) ; CON6101.7@1872.25,775.18 1872.25,776.02 v2(1872.31,776.09)
  Bottom w10: v2(1816.65,3711.09) 1825.15,3711.09 R3232.1@1835.65,3700.59
  Bottom w12: v2(500.73,3548.01) 521.31,3527.42 521.31,3445.94 599.17,3368.09 v2(740.31,3368.09) ; v2(711.33,2693.61) 737.31,2719.6 737.31,2738.09 761.31,2762.09 858.25,2762.09 889.25,2793.09 1274.31,2793.09 v2(1287.31,2806.09) ; v2(1294.31,3216.09) v2@1294.7,3216.09 ; v2(1294.81,3228.88) 1294.98,3228.71 1294.7,3228.43 v2@1294.7,3216.09 ; v2(1394.95,4144.49) R1208.1@1394.95,4108.49 1422.54,4108.49 v2(1422.54,4108.8) ; R1209.1@1395.95,4046.49 v2@1419.3,4046.49 ; R1009.2@1414.31,4017 1414.31,4041.5 v2@1419.3,4046.49 ; v2(1422.86,4050.06) v2@1419.3,4046.49 ; v2(1678.46,3452.31) 1697.65,3452.31 R3278.1@1697.65,3450.59 ; v2(1683.31,3827.09) 1683.31,3861.77 1724.4,3902.86 1724.4,4004.34 v2(1731.15,4011.09) ; v2@1294.7,3216.09 1350.06,3216.09 ; 1350.06,3216.09 1363.31,3216.09 v2(1366.04,3214.91) v2(1366.04,3227.15) 1365.69,3227.5 1361.47,3227.5 1350.06,3216.09
VIO28_PMU: C2047.1 C6313.1 C6315.1 R6105.2 R6307.2 R6311.1 R6313.1 R6350.1 U2001.K2 U6301.A1 U6301.A2 U6303.7 | length 6055.4
  Top w4: v1(155.04,4169.72) 154.95,4169.83 R6307.2@155.95,4169.83 ; v1(913.31,3328.09) C2047.1@918.31,3328.09
  Top w8: U6301.A2@1286.95,4442.74 U6301.A1@1302.7,4442.74
  Top w10: R6350.1@714.88,4720.78 723.66,4711.99 1204.81,4711.99 1275.31,4641.49
  Top w12: v1(464.31,3582.09) 464.31,3584.09 505.94,3584.09 613.31,3476.71 613.31,3367.83 ; v1(519.31,3253.83) 519.54,3253.6 529.02,3263.09 598.55,3263.09 608.29,3272.83 v1(628.95,3272.83) ; v1(633.45,3321.83) 613.31,3341.96 613.31,3367.83 ; v1(687.31,3367.61) 687.09,3367.83 613.31,3367.83 ; U6301.A2@1286.95,4442.74 1286.95,4437.29 1277.14,4427.49 1258.95,4427.49 C6315.1@1243.95,4442.49 1243.95,4449 1239.31,4453.64 1239.31,4495.09 1236.77,4497.63 1236.77,4602.95 1275.31,4641.49 1335.95,4641.49 1339.48,4637.96 U6303.7@1339.48,4613.48 1339.48,4611.49 C6313.1@1369.95,4611.49 1369.95,4648.68 1384.5,4663.22 1396.5,4663.22 v1(1398.69,4661.36)
  Inner Layer 2 w8: v1(913.31,3328.09) 913.24,3328.02 923.31,3317.94 923.31,3274.3 931.33,3266.29 v4(931.33,3243.19)
  Inner Layer 2 w10: v1(687.31,3367.61) 687.31,3368.21 701.93,3382.83 731.61,3382.83 773.35,3341.09 838.58,3341.09 839.58,3342.09 901.52,3342.09 913.31,3330.3 v1(913.31,3328.09)
  Inner Layer 2 w12: v1(155.04,4169.72) 154.95,4170.83 154.95,4221.83 272.95,4339.83 v3(290.95,4339.83) ; v3(442.09,2692.15) 438.76,2690.63 421.31,2673.19 421.31,2645.94 503.31,2563.94 v1(503.31,2553.09) ; v3(442.72,3155.36) 484.31,3196.95 484.31,3240.67 497.48,3253.83 v1(519.31,3253.83) ; v1(464.31,3582.09) 462.31,3580.09 462.31,3578.85 455.55,3572.09 455.34,3572.09 451.34,3568.09 428.74,3568.09 397.31,3599.52 397.31,3630.54 400.95,3634.18 400.95,4089.09 433.7,4121.83 433.94,4121.83 523.95,4211.84 523.95,4250.86 577.31,4304.22 577.31,4401.21 583.47,4407.36 583.47,4460.11 v3(582.41,4460.11) ; v1(628.95,3272.83) 625.91,3275.87 625.91,3314.3 v1(633.45,3321.83) ; v1(1398.69,4661.36) 1398.46,4663.22 1398.46,4677.7 v3(1400.42,4677.7)
  Inner Layer 4 w12: v3(442.09,2692.15) 441.18,2693.06 453.31,2705.19 453.31,2918.19 398.31,2973.19 398.31,3110.95 v3(442.72,3155.36) ; v3(582.41,4460.11) 583.47,4461.17 585.55,4463.13 585.55,4481.36 652.28,4548.09 744.31,4548.09 819.31,4623.09 1056.22,4623.09 1097.31,4582 1097.31,4556.97 1126.19,4528.09 1167.19,4528.09 1169.19,4526.09 1248.8,4526.09 v3(1400.42,4677.7)
  Inner Layer 5 w12: v3(290.95,4339.83) 288.95,4339.83 288.95,4414.09 337.99,4463.13 583.47,4463.13 583.47,4461.17 v3(582.41,4460.11) ; v3(1400.42,4677.7) 1400.1,4678.02 1413.27,4691.18 v2(1412.95,4691.49) ; v2(1599.55,4446.43) 1605.42,4452.3 1604.95,4452.77 v2(1604.95,4623.49)
  Bottom w4: R6313.1@1655.31,4459.09 1653.95,4460.49 R6313.1@1655.31,4459.12
  Bottom w12: v2(1412.95,4691.49) 1422.22,4682.22 1458.83,4682.22 1516.37,4624.69 1516.37,4622.49 1580.95,4622.49 1581.95,4623.49 v2(1604.95,4623.49) ; v2(1599.55,4446.43) 1599.55,4447.14 1613.74,4461.33 1618.31,4461.33 R6311.1@1618.31,4461.09 1618.31,4460.09 1654.31,4460.09 1655.31,4459.09 R6313.1@1656.31,4459.09
VLTE_PMIC_FB: SH1004.1 U2001.C14 | length 1093.1
  Inner Layer 2 w4: v4(1041.57,3054.22) 1041.56,3067.51 1046.42,3072.36 v3(1046.84,3071.94)
  Inner Layer 5 w4: v3(1046.84,3071.94) 1046.93,3072.88 1046.93,3113.92 1143.95,3210.94 1143.95,3260.09 1111.31,3292.73 1111.31,3346.62 1120.59,3355.89 1136.61,3355.89 1177.95,3397.23 1177.95,3423.58 1202.35,3447.98 1202.35,3463.25 1214.31,3475.21 1214.31,3509.36 1217.31,3512.36 1217.31,3568.79 v2(1202.21,3583.89)
  Bottom w4: v2(1202.21,3583.89) 1207.02,3579.09 1353.63,3579.09 1417.31,3642.78 1417.31,3814.29 1401.51,3830.09 ; SH1004.1@1397.31,3838.09 1397.31,3834.34 1401.51,3830.14
VLTE_PMU: L2003.2 R1007.1 R1013.1 | length 118.5
  Top w12: 1359.31,3091.09 1362.31,3094.09 R1007.1@1362.31,3123.09
  Top w20: L2003.2@1318.53,3057.49 1318.52,3072.09 1337.52,3091.09 1359.31,3091.09 R1013.1@1381.31,3091.09
VLTE_SRAM: C10007.1 C10010.1 R1007.2 R1011.2 U1001.AC16 U1001.AC20 U1001.AC24 | length 1602.1
  Top w4: R1011.2@1399.31,2951.09 1399.31,2950.09 v1(1405.31,2950.09)
  Top w8: v4(1329.19,3905.49) 1337.46,3905.49 ; U1001.AC20@1329.19,3968.48 1347.08,3968.48 ; U1001.AC24@1329.19,4031.47 1339.7,4031.47
  Top w12: 1339.7,4031.47 1347.08,4024.1 1347.08,3968.48 ; R1007.2@1382.31,3123.09 v1(1382.31,3137.09) v1(1382.31,3149.09)
  Top w14: 1337.46,3905.49 1347.08,3915.11 1347.08,3968.48
  Inner Layer 2 w12: v4(1329.19,3905.49) 1338.46,3905.49 1346.08,3913.1 v3(1346.18,3914.96) ; v1(1382.31,3137.09) 1383.31,3137.09 1383.31,3149.09 v1(1382.31,3149.09) 1382.31,3188.09 v3(1383.31,3188.09) ; v1(1405.31,2950.09) 1414.31,2959.09 1414.31,2974.84 1406.95,2982.21 v3(1406.95,3002.12)
  Inner Layer 4 w12: v3(1346.18,3914.96) 1346.08,3913.1 1328.31,3895.33 1328.31,3807.13 1485.38,3650.06 1485.38,3606.7 1516.69,3575.4 v3(1531.69,3575.4) 1531.69,3565.11 1511.23,3544.66 1511.23,3465.83 v3(1515.9,3460.12)
  Inner Layer 5 w12: v2(1325.95,3190.09) 1325.95,3139.45 1406.95,3058.45 v3(1406.95,3002.12) ; v2@1368.12,3188.13 v3(1383.31,3188.09) ; v2(1511.31,3585.09) 1508.92,3585.09 1508.92,3573.09 1531.69,3573.09 v3(1531.69,3575.4)
  Inner Layer 5 w15: v3(1383.31,3188.09) 1384.31,3189.13 1384.31,3366.26 1478.17,3460.12 v3(1515.9,3460.12)
  Bottom w12: v2(1325.95,3190.09) 1368.12,3190.09 v2(1368.12,3188.18) ; C10010.1@1509.31,3609.09 1509.31,3583.09 C10007.1@1513.31,3583.09
VLTE_SRAM_ID: R1109.1 U1001.AD5 | length 241.3
  Top w4: v4(1344.94,3732.26) U1001.AD5@1344.93,3732.47 ; v1(1464.68,3572.66) v1(1464.68,3572.66) 1480.32,3557.09 R1109.1@1489.31,3557.09
  Inner Layer 2 w4: v4(1344.94,3732.26) 1357.31,3719.88 1357.31,3692.99 1361.31,3688.99 1361.31,3678.59 1413.45,3626.45 1413.45,3625.62 1465.58,3573.49 v1(1464.68,3572.66) v1(1464.68,3572.66)
VLTE_SW: L2003.1 U2001.A12 U2001.B12 U2001.C12 | length 401.6
  Top w4: L2003.1@1258.95,3064.48 1258.95,3063.91 L2003.1@1265.38,3057.49
  Top w8: U2001.C12@1041.57,3085.71 U2001.B12@1057.32,3085.71 U2001.A12@1073.06,3085.71 1081.31,3085.71 ; 1081.31,3085.71 1090.69,3085.71 ; 1081.31,3085.71 1090.69,3085.71 ; 1090.69,3085.71 1092.58,3083.82 1096.31,3083.82 1096.31,3085.71 1090.69,3085.71
  Top w20: 1096.31,3083.82 1183.96,3083.82 ; 1183.96,3083.82 1254.54,3083.82 1265.88,3072.48 L2003.1@1265.88,3064.48 ; 1183.96,3083.82 1183.96,3064.48 1258.95,3064.48 L2003.1@1265.88,3064.48 ; L2003.1@1265.88,3047.83 L2003.1@1265.38,3057.49 L2003.1@1265.88,3047.83 ; L2003.1@1265.88,3047.83 L2003.1@1265.88,3064.48
VM: R1005.1 R2403.1 U2001.J1 | length 629
  Top w4: R1005.1@897.54,3589.49 897.54,3591.49 930.14,3624.09 v1(946.31,3624.09)
  Top w8: 946.31,3280.83 946.31,3258.94 U2001.J1@947.08,3258.94 ; 946.31,3351.47 947.95,3349.83
  Top w12: 946.31,3280.83 946.31,3344.62 ; 946.31,3344.62 937.95,3352.98 937.95,3391.65 944.13,3397.83 944.95,3397.83 946.31,3396.47 946.31,3351.47 946.31,3344.62
  Top w25: R1005.1@897.54,3589.49 897.54,3546.52 944.95,3499.11 944.95,3397.83
  Inner Layer 2 w4: v3(931.31,3626.09) 931.31,3625.09 946.31,3625.09 v1(946.31,3624.09)
  Inner Layer 5 w4: v2(858.97,3613.16) 858.97,3611.32 916.54,3611.32 v3(931.31,3626.09)
  Bottom w4: v2(858.97,3613.16) 858.97,3592.75 867.2,3584.52 867.2,3564.11 R2403.1@866.2,3564.11
VM_EXT: C2411.1 C2413.1 L2401.2 R1021.1 R2416.2 | length 305.6
  Inner Layer 2 w4: v3(723.37,3626.38) 723.29,3625.15 723.39,3624.92 v3@723.39,3624.86
  Inner Layer 5 w4: v2(678.32,3618.21) 678.32,3618.52 691.15,3618.52 v2(691.15,3618.83) 699.15,3626.83 705.24,3626.83 705.24,3626.66 v3(705.21,3626.19) 705.27,3626.2 705.27,3626.14 705.21,3624.92 723.29,3624.92 723.29,3625.15 v3(723.37,3626.38)
  Bottom w10: C2413.1@684.31,3609.09 684.31,3609.2 691.15,3609.2 R2416.2@705.8,3609.2
  Bottom w12: L2401.2@641.72,3525.11 641.72,3594.49 656.31,3609.09 C2413.1@684.31,3609.09 ; v2(653.24,3618.74) v2(665.64,3618.74) 674.75,3618.74 682.91,3610.58 C2413.1@684.29,3609.2
  Bottom w25: L2401.2@641.72,3525.11 643.72,3525.11 C2411.1@643.72,3450.09
  other v1: 677.13,3624.48 689.7,3624.48 651.57,3624.93 664.38,3624.68
VMC_PMU: R1016.2 U2001.K4 | length 416
  Top w8: U2001.K4@931.33,3211.7 v4(931.31,3227.43)
  Top w12: R1016.2@995.31,3505.09 995.31,3504.09 994.31,3504.09 984.31,3494.09 984.31,3430.66 v1(1000.88,3414.09)
  Inner Layer 2 w8: v3@908.3,3281.09 907.31,3279.09 v3(904.31,3279.09) 907.31,3278.09 907.31,3271.77 918.3,3260.78 918.3,3237.84 928.71,3227.43 v4(931.31,3227.43)
  Inner Layer 2 w10: v1(1000.88,3414.09) 1023.95,3391.02 v3(1023.95,3380.83)
  Inner Layer 5 w4: v3(904.31,3279.09) 907.31,3279.09 v3@908.68,3280.71
  Inner Layer 5 w10: v3(904.31,3279.09) 924.31,3299.09 964.3,3299.09 1019.95,3354.75 1019.95,3376.83 v3(1023.95,3380.83) ; v3@907.31,3279.09 v3@908.68,3279.09 ; v3@908.68,3277.98 v3@908.68,3279.09 ; v3@908.68,3280.71 v3@908.68,3279.09
VMCH_PMU: R4001.2 U2001.R9 | length 2810.2
  Top w8: 698.36,3137.59 701.86,3134.09 742.95,3134.09 747.95,3129.09 847.32,3129.09 848.32,3130.09 849.72,3130.09 U2001.R9@852.59,3132.96
  Top w12: v1(539.84,3174.77) 540.01,3174.95 548.84,3166.12 v1(549.01,3166.29) ; R4001.2@689.95,1237.49 v1(690.95,1237.49) 690.95,1251.72 v1(691.31,1251.09)
  Top w15: v1(427.31,2894.09) v1(439.31,2906.09) 439.31,2956.09 483.26,3000.04 v1@483.26,3076.09 ; v1(471.32,3089.12) 480.2,3080.24 484.31,3076.13 484.31,3075.04 ; v1(480.07,3080.1) 481.48,3078.95 v1@483.26,3076.09 ; v1@548.62,3166.68 v1(549.01,3166.29) 559.98,3155.33 680.62,3155.33 698.36,3137.59 ; v1@483.26,3076.09 484.23,3075.12 ; 484.23,3075.12 484.31,3075.04 ; 484.23,3075.12 484.23,3071.01 484.31,3071.09 484.31,3075.04
  Inner Layer 2 w4: v1@690.95,1252.09 691.31,1252.09 v1(691.31,1251.09)
  Inner Layer 2 w10: v1(471.32,3089.12) 539.84,3157.64 v1(539.84,3174.77)
  Inner Layer 2 w12: v1(480.07,3080.1) 478.84,3081.6 548.59,3151.35 548.59,3165.91 v1(549.01,3166.29)
  Inner Layer 2 w15: v3(330.54,2745.83) 330.54,2828.49 396.14,2894.09 v1(427.31,2894.09) v1(439.31,2906.09)
  Inner Layer 2 w20: v3(433.95,1550.37) 435.23,1549.09 463.31,1549.09 690.95,1321.45 690.95,1252.09 v1(690.95,1237.49)
  Inner Layer 4 w18: 280.31,2700.81 325.33,2745.83 v3(330.54,2745.83)
  Inner Layer 4 w20: 280.31,2700.81 280.31,2387.68 223.31,2330.68 223.31,1883.11 409.31,1697.11 409.31,1575.01 v3(433.95,1550.37)
VPA_PMU: C2055.1 C3290.1 L2009.2 R3224.2 R3234.2 U2001.B14 | length 638.9
  Top w4: v1(1197.39,2959.49) 1232.64,2959.49 L2009.2@1232.64,2961.89 ; v1(1272.8,2940.45) 1272.8,2952.4 1273.95,2953.55 C2055.1@1273.95,2969.49
  Top w20: L2009.2@1232.64,2961.89 1232.64,2969.49 C2055.1@1273.95,2969.49
  Inner Layer 2 w4: v4(1057.32,3054.22) 1066.78,3054.22 1067.64,3055.08 1085.93,3055.08 1093.18,3047.83 1131.92,3047.83 1142.08,3037.67 1142.08,3016.01 1147.35,3010.74 1174.26,3010.74 1197.39,2987.6 v1(1197.39,2959.49) ; v1(1273.05,2928.45) 1273.43,2928.82 1280.87,2921.38 v3(1280.87,2910.38)
  Inner Layer 4 w30: v3(1262.24,2909.91) 1513.15,2909.91 1519.98,2916.74 v3(1532.37,2916.74) v3(1550.97,2916.74)
  other v1: 1532.31,2866.09 1546.31,2866.09 1532.31,2878.09 1546.31,2878.09 1532.31,2891.09 1546.41,2890.64 1247.31,2928.09 1260.45,2928.64 1247.65,2940.87 1260.39,2940.71
VPA_SW: L2009.1 U2001.A15 | length 194.7
  Top w4: L2009.1@1170.47,2984.12 L2009.1@1176.72,2990.37
  Top w8: 1096.95,3022.49 1092.22,3022.49 1076.24,3038.47 U2001.A15@1073.06,3038.47 ; U2001.A15@1073.06,3038.47 1073.64,3039.05 U2001.A15@1073.06,3038.47
  Top w20: 1096.95,3022.49 1097.29,3022.49 1097.79,3021.99 1097.79,3017.17 1105.26,3009.71 1157.39,3009.71 1176.72,2990.37 1176.72,2961.49 L2009.1@1173.59,2961.89 1170.47,2961.49 L2009.1@1170.47,2984.12
VPA_VCC1: C3244.1 C3245.1 R3220.1 R3224.1 U3203.29 | length 2009.5
  Top w4: v1(1584.31,2893.09) 1584.73,2892.66 1584.31,2889.09 1586.31,2887.09 R3224.1@1586.31,2883.09 ; R3220.1@1918.31,3017.56 1918.31,3018.56 v1(1919.43,3019.68)
  Inner Layer 2 w10: v1(1584.31,2893.09) 1611.58,2893.09 1656.45,2848.21 1656.45,2846.16 1683.31,2819.3 1736.79,2819.3 1776.95,2859.46 1776.95,2922.44 1851.81,2997.3 1897.05,2997.3 v1(1919.43,3019.68) 1964.15,3064.4 1964.15,3161.74 2014.5,3212.09 v3(2039.65,3212.09)
  Inner Layer 5 w4: v2(2105.52,3563.29) 2105.59,3563.29 2105.59,3556.94 2105.59,3550.66 2105.59,3550.59 v2(2105.65,3550.59)
  Inner Layer 5 w9: v3(2039.65,3212.09) 2094.45,3212.09 2134.07,3251.71 2235.28,3251.71 2349.3,3365.73 2349.3,3435.7 2353.15,3439.55 2353.15,3448.6 2375.65,3471.09 2377.66,3471.09 2419.81,3513.24 2419.81,3623.16 2403.98,3638.99 2278.86,3638.99 v2(2276.43,3636.57)
  Inner Layer 5 w12: v2(2033.94,3521.46) 2040.81,3514.59 2082.65,3514.59 v2(2105.65,3537.59) v2(2105.65,3550.59) ; v2(2105.52,3563.29) 2105.52,3557 ; 2105.52,3557 2105.52,3550.72 2105.59,3550.66 v2(2105.65,3550.59) ; 2105.52,3557 2105.59,3556.94 2105.65,3556.87 v2(2105.65,3550.59)
  Bottom w4: U3203.29@2024.55,3525.59 2024.55,3525.87 2028.96,3525.87 2033.66,3521.18 v2(2033.94,3521.46) ; C3245.1@2105.65,3535.59 v2(2105.65,3537.59)
  Bottom w9: C3244.1@2105.65,3560.59 2116.15,3560.59 2122.62,3567.06 2122.62,3592.62 2104.15,3611.09 2104.15,3643.09 2114.73,3653.67 2167.04,3653.67 2177.65,3643.06 2179.28,3643.06 ; 2179.32,3643.09 2180.94,3643.09 2181.94,3642.09 2227.29,3642.09 2232.81,3636.57 v2(2276.43,3636.57)
  Bottom w12: v2(2105.52,3563.29) C3244.1@2105.65,3563.16 ; v2(2105.65,3550.59) C3244.1@2105.65,3560.59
